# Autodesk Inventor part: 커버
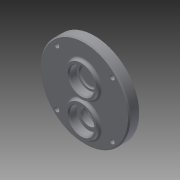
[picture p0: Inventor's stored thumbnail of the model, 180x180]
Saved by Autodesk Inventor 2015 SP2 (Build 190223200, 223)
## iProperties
Created: 2015-06
Part Number: 커버
Material: 일반
Document SubType Name: Modeling
Designer: AMC
Density: 1 g/cm^3
Appearance: 기본값
Author: AMC
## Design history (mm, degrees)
sketch "스케치1"
  geometry: C1 r 40 at (0, 0); 1 further point
  constraints: 1 centre point, 1 coincident
  dimensions: "d0" = 80 diameter of C1
extrude "돌출1" new body sketch "스케치1" distance "d1" = 9; taper "d2" = 0 deg
sketch "스케치2"
  geometry: C1 r 15 at (0, -20); 1 further point
  constraints: 1 centre point, 1 vertical alignment
  dimensions: "d3" = 20 distance of C1.centre point (0, 0); "d4" = 30 diameter of C1
extrude "돌출2" join sketch "스케치2" distance "d5" = 4; taper "d6" = 0 deg
sketch "스케치3"
  geometry: C1 r 14 at (0, -20); C2 r 14 at (0, 11); 1 further point
  constraints: 2 centre point, 2 vertical alignment
  dimensions: "d7" = 11 distance of point (0, 0) C2.centre; "d8" = 20 distance of point (0, 0) C1.centre; "d9" = 28 diameter of C2; "d10" = 28 diameter of C1
extrude "돌출3" join sketch "스케치3" distance "d11" = 3; taper "d12" = 0 deg
hole "구멍1" diameter "d15" = 15; stored, may be unused: countersink angle "d19" = 90 deg, drill point angle "d21" = 118 deg; dims "d13" = 10, "d14" = 10, "d16" = 6, "d17" = 22, "d18" = 7, "d20" = 8
hole "구멍2" diameter "d24" = 15; stored, may be unused: countersink angle "d28" = 90 deg, drill point angle "d30" = 118 deg; dims "d22" = 10, "d23" = 10, "d25" = 6, "d26" = 22, "d27" = 7, "d29" = 8
hole "구멍3" diameter "d33" = 18; stored, may be unused: countersink angle "d37" = 90 deg, drill point angle "d39" = 0 deg; dims "d34" = 6, "d35" = 22, "d36" = 7, "d38" = 8, "d42" = 10, "d43" = 10
fillet "모깎기1" dims "d40" = 0.3
fillet "모깎기3" dims "d44" = 2
chamfer "모따기1" distance "d45" = 1; stored, may be unused: second distance "d46" = 2, angle "d47" = 45 deg
chamfer "모따기2" distance "d48" = 1; stored, may be unused: second distance "d49" = 2, angle "d50" = 45 deg
fillet "모깎기4" dims "d51" = 2
sketch "스케치4"
  geometry: L1 (24.749, 24.749)-(0, 0); L2 (0, 0)-(40, 0); 1 further point
  constraints: 4 end point, 1 horizontal, 1 horizontal alignment, 1 other
  dimensions: "d52" = 45 deg angle of L1 L2; "d53" = 35 distance of L1.start L1.end
hole "구멍4" sketch "스케치4" at (24.749, 24.749) diameter "d54" = 4.5; stored, may be unused: countersink angle "d58" = 90 deg, drill point angle "d60" = 118 deg; dims "d55" = 6, "d56" = 8, "d57" = 4.4, "d59" = 8
node "솔리드1"
pattern_circular "원형 패턴1" dims angle "d62" = 360 deg
